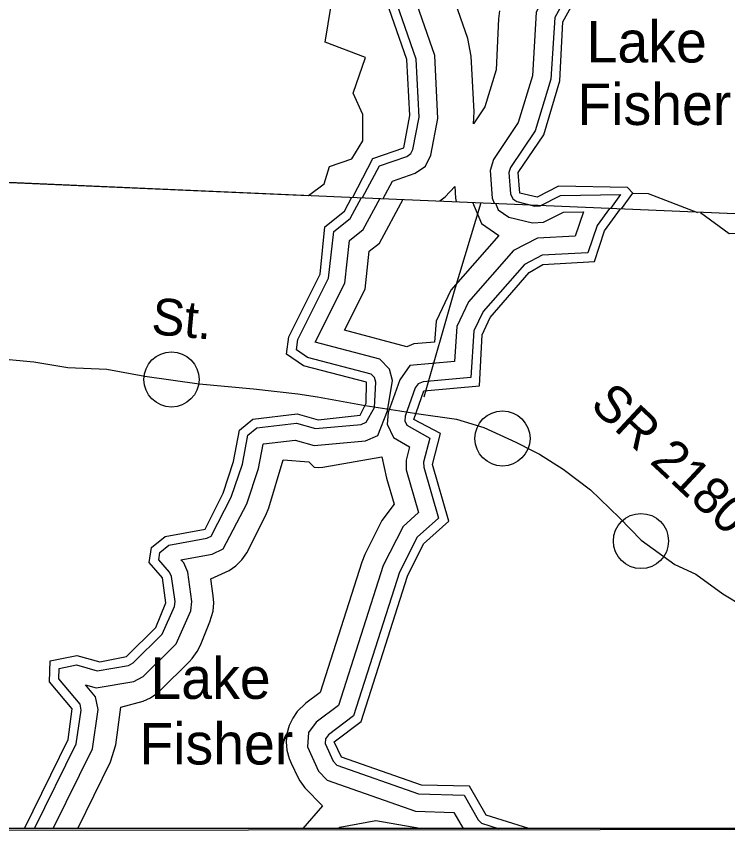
# Model space of a CAD drawing. Extents: x 1530800 to 1534168, y 642962 to 645162.
# Drawn here: x 1531509.4 to 1531702.7, y 644498.9 to 644725.7 of the extents above; entities that cross this region are included whole.
import ezdxf

# ---------------------------------------------------------------- set-up
doc = ezdxf.new("R2010")
doc.units = 0
for name, color, linetype in [('Old_Level_1', 7, 'Continuous'), ('Old_Level_11', 7, 'Continuous'), ('Old_Level_21', 7, 'Continuous'), ('Old_Level_29', 7, 'Continuous'), ('Old_Level_32', 7, 'Continuous'), ('Old_Level_49', 7, 'Continuous'), ('Old_Level_52', 7, 'Continuous'), ('Old_Level_59', 7, 'Continuous'), ('Old_Level_60', 7, 'Continuous'), ('Old_Level_61', 7, 'Continuous')]:
    doc.layers.add(name, color=color, linetype=linetype)

msp = doc.modelspace()

# ---------------------------------------------------------------- linework, layer by layer
at = {"layer": 'Old_Level_1'}
for centre in [(1531551.47, 644626.99), (1531641.5, 644610.94), (1531679.18, 644583.03)]:
    msp.add_circle(centre, 7.5, dxfattribs=at)
at = {"layer": 'Old_Level_29'}
for points in [[(1531285.1, 645044.6), (1531955.36, 645044.6), (1531955.36, 644504.86), (1531285.1, 644504.86)], [(1531285.1, 644504.21), (1531955.36, 644504.86), (1531955.44, 644422.92), (1531285.18, 644422.27)]]:
    msp.add_lwpolyline(points, close=True, dxfattribs=at)
msp.add_lwpolyline([(1531954.88, 644504.86), (1531284.62, 644504.86)], dxfattribs=at)
at = {"layer": 'Old_Level_32'}
for points in [[(1531454.41, 644646.09), (1531467.57, 644641.36), (1531481.68, 644637.23), (1531492.88, 644634.03), (1531502.42, 644632.85), (1531514.02, 644631.77), (1531523.24, 644630.23), (1531533.86, 644629.78), (1531544.2, 644627.84), (1531559.04, 644625.83), (1531573.76, 644624.43), (1531585.86, 644623.09), (1531591.22, 644622.24), (1531604.18, 644619.88), (1531613.6, 644618.44)], [(1531613.6, 644618.44), (1531618.15, 644617.75), (1531628.98, 644616.18), (1531636.45, 644613.92), (1531645.13, 644609.89), (1531649.96, 644607.45), (1531651.56, 644606.64), (1531658, 644602.61), (1531665.41, 644597), (1531673.3, 644589.37), (1531679.21, 644583.28), (1531688.35, 644576.63), (1531694.09, 644574.01), (1531701.48, 644568.68), (1531707.14, 644565.24), (1531712.46, 644561.98), (1531722.65, 644556.98)]]:
    msp.add_lwpolyline(points, dxfattribs=at)
at = {"layer": 'Old_Level_49'}
msp.add_line((1531592.97, 644680.21), (1531594.48, 644684.9), dxfattribs=at)
for points in [[(1531594.48, 644684.9), (1531600.5, 644686.97), (1531603.54, 644691.89), (1531603.54, 644699.09), (1531600.86, 644704.86), (1531604.21, 644714.56), (1531593.27, 644718.77), (1531599.26, 644755.34), (1531602.71, 644760.06), (1531597.99, 644803.72), (1531515.37, 644810.8), (1531524.81, 644837.94), (1531450.45, 644839.12), (1531323.02, 644842.1), (1531285.94, 644842.88)], [(1531285.1, 644694.34), (1531324.69, 644691.72), (1531465.61, 644682.42), (1531588.73, 644677.01)], [(1531588.73, 644677.01), (1531592.97, 644680.21)]]:
    msp.add_lwpolyline(points, dxfattribs=at)
at = {"layer": 'Old_Level_52'}
msp.add_lwpolyline([(1531954.91, 644663.36), (1531779.67, 644668.88), (1531597.73, 644676.59), (1531466.06, 644682.38), (1531325.14, 644691.67), (1531285.1, 644694.33)], dxfattribs=at)
at = {"layer": 'Old_Level_59'}
for points in [[(1531676.97, 644677.71), (1531681.16, 644677.62), (1531694.54, 644672.41)], [(1531695.36, 644672.37), (1531703.15, 644666.72), (1531711.46, 644666.76), (1531722.33, 644663.87), (1531738.34, 644670.79)]]:
    msp.add_lwpolyline(points, dxfattribs=at)
at = {"layer": 'Old_Level_60'}
for points in [[(1531676.97, 644677.71), (1531675.47, 644679.17), (1531656.72, 644679.55), (1531650.91, 644676.59), (1531646.22, 644677.71), (1531645.78, 644683.26), (1531652.72, 644693.58), (1531657.15, 644708.26), (1531657.9, 644724.25), (1531665.41, 644737.84), (1531664.47, 644742.99), (1531657.78, 644746.82), (1531660.54, 644761.62), (1531658.32, 644768.84), (1531659.3, 644785.6), (1531654.78, 644796.89), (1531652.87, 644803.15), (1531650.97, 644811.14), (1531637.08, 644811.66), (1531637.47, 644816.37), (1531655.28, 644820.32), (1531656.91, 644823.36)], [(1531600.79, 644676.58), (1531606.28, 644687.13), (1531614.66, 644690.04), (1531616.34, 644698.83), (1531615.53, 644714.03), (1531606.6, 644739.64)], [(1531568.38, 644604.7), (1531569.96, 644613.19), (1531573.64, 644616.2), (1531585.64, 644617.6), (1531591.33, 644616.05), (1531602.83, 644617.25), (1531604.46, 644620.5), (1531604.52, 644626.24), (1531587.39, 644630.69), (1531582.77, 644633.86), (1531583.39, 644638.57), (1531591.96, 644655.63), (1531593.21, 644668.53), (1531598.52, 644672.73), (1531600.53, 644676.59)], [(1531673.84, 644673.37), (1531676.97, 644677.71)], [(1531622.47, 644603.83), (1531624.64, 644612.3), (1531617.4, 644616.13), (1531620.14, 644623.87), (1531635.27, 644625.21), (1531636.02, 644639.15), (1531638.14, 644643.82), (1531648.77, 644656.12), (1531652.46, 644658.3), (1531666.52, 644659.05), (1531669.27, 644667.4), (1531673.58, 644673.38)], [(1531511.47, 644504.86), (1531523.33, 644529), (1531524.46, 644537.38), (1531518.33, 644544.69), (1531518.46, 644550.43), (1531525.77, 644551.92), (1531531.96, 644550.16), (1531539.27, 644551.65), (1531547.2, 644559.49), (1531549.96, 644566.21), (1531549.02, 644573), (1531545.4, 644577.17), (1531546.02, 644581.26), (1531549.71, 644584.27), (1531560.65, 644586.3), (1531565.52, 644596.05), (1531568.38, 644604.7)], [(1531648.64, 644504.86), (1531637.08, 644508.44), (1531632.52, 644516.33), (1531619.52, 644516.59), (1531597.7, 644524.21), (1531595.7, 644528.36), (1531603.08, 644533.95), (1531615.7, 644573.5), (1531620.02, 644582.23), (1531626.89, 644588.45), (1531622.47, 644603.83)]]:
    msp.add_lwpolyline(points, dxfattribs=at)
at = {"layer": 'Old_Level_61'}
for points in [[(1531609.07, 644676.25), (1531611.59, 644680.93), (1531617.8, 644683.09), (1531620.59, 644685.02), (1531621.99, 644687.97), (1531623.92, 644697.99), (1531623.09, 644715.13), (1531614.17, 644740.97), (1531613.93, 644758.72), (1531612.37, 644764), (1531616.87, 644775.61), (1531622.73, 644781.71), (1531624.25, 644784.72), (1531624.39, 644791.09), (1531623.48, 644794.55), (1531620.09, 644797.59), (1531623.45, 644798.22), (1531626.41, 644799.5), (1531629.89, 644803.68)], [(1531629.89, 644803.68), (1531635.89, 644798.26), (1531638.28, 644797.09), (1531642.72, 644796.21), (1531645.13, 644794.13), (1531646.74, 644790.8), (1531647.4, 644768.14), (1531649.44, 644762.86), (1531650.23, 644745.64), (1531651.75, 644741.74), (1531657.11, 644738.53), (1531650.7, 644726.92), (1531649.63, 644709.59), (1531645.78, 644696.87), (1531639.05, 644686.86), (1531638.13, 644683.82), (1531638.7, 644676.31), (1531639.25, 644674.98)], [(1531633.6, 644696.5), (1531633.82, 644699.76), (1531633.01, 644714.96), (1531632.05, 644719.79), (1531624.06, 644742.73)], [(1531603.4, 644676.48), (1531608.04, 644685.1), (1531615.48, 644687.68), (1531616.57, 644688.44), (1531617.11, 644689.57), (1531618.8, 644698.35), (1531618.03, 644714.16), (1531609.09, 644740.09)], [(1531662.79, 644738.27), (1531655.72, 644725.46), (1531654.67, 644708.69), (1531650.44, 644694.66), (1531643.7, 644684.65), (1531643.28, 644683.26), (1531643.72, 644677.51), (1531644.31, 644676.1), (1531645.37, 644675.36), (1531650.33, 644674.16), (1531651.76, 644674.24), (1531657.3, 644677.04), (1531673.58, 644677.3)], [(1531640.67, 644727.29), (1531640.42, 644725.07), (1531639.78, 644711.25), (1531636.73, 644701.16), (1531633.6, 644696.5)], [(1531624.44, 644675.61), (1531625.9, 644676.64), (1531628.52, 644679.45)], [(1531628.52, 644679.45), (1531628.77, 644676.33), (1531628.89, 644675.42)], [(1531585.45, 644635.05), (1531585.82, 644637.82), (1531594.19, 644654.51), (1531595.59, 644667.22), (1531600.07, 644670.77), (1531603.14, 644676.48)], [(1531590.57, 644637.12), (1531598.64, 644653.19), (1531599.92, 644664.83), (1531603.64, 644667.77), (1531608.21, 644676.28)], [(1531598.5, 644640.36), (1531604.13, 644651.57), (1531605.26, 644661.87), (1531608.05, 644664.08), (1531614.47, 644676.03)], [(1531673.58, 644677.3), (1531670.86, 644673.51)], [(1531670.6, 644673.52), (1531667.24, 644668.86), (1531664.68, 644661.45), (1531652.32, 644660.8), (1531647.5, 644658.27), (1531636.25, 644645.46), (1531633.75, 644640.18), (1531632.89, 644627.51), (1531619.93, 644626.36), (1531618.54, 644625.79), (1531617.79, 644624.73), (1531615.04, 644616.97), (1531614.93, 644615.7), (1531615.48, 644614.53), (1531621.73, 644611.01), (1531620.05, 644604.45), (1531620.07, 644603.14), (1531624.06, 644589.26), (1531618.34, 644584.09), (1531613.47, 644574.6), (1531600.94, 644535.47), (1531594.2, 644530.35), (1531593.35, 644529.21), (1531593.24, 644527.92), (1531595.45, 644523.12), (1531596.45, 644522.05), (1531618.69, 644514.23), (1531631.06, 644513.86), (1531634.92, 644507.19), (1531635.83, 644506.28), (1531640.34, 644504.86)], [(1531620.23, 644622.29), (1531628.48, 644651.14), (1531635.67, 644675.17)], [(1531633.37, 644675.23), (1531635.77, 644669.45), (1531640.49, 644666.16)], [(1531639.58, 644674.97), (1531640.34, 644673.13), (1531643.2, 644671.14), (1531649.65, 644669.57), (1531652.71, 644669.75), (1531658.15, 644672.5), (1531663.53, 644672.59)], [(1531663.53, 644672.59), (1531661.25, 644666.01), (1531651.04, 644665.47), (1531644.53, 644662.05), (1531632.27, 644648.08), (1531629.09, 644641.4), (1531628.45, 644631.86), (1531616.27, 644630.79)], [(1531640.49, 644666.16), (1531627.42, 644651.27), (1531623.43, 644642.88), (1531623.04, 644637.16), (1531617.4, 644636.66), (1531615.48, 644635.86)], [(1531615.48, 644635.86), (1531598.5, 644640.36)], [(1531608.12, 644632.47), (1531590.57, 644637.12)], [(1531514.25, 644504.86), (1531525.57, 644527.9), (1531526.94, 644537.05), (1531526.62, 644538.63), (1531520.85, 644545.57), (1531520.91, 644548.38), (1531525.67, 644549.35), (1531531.27, 644547.75), (1531539.77, 644549.2), (1531541.03, 644549.87), (1531548.97, 644557.71), (1531552.27, 644565.26), (1531552.43, 644566.55), (1531551.5, 644573.34), (1531550.93, 644574.6), (1531548.04, 644577.94), (1531548.34, 644579.93), (1531550.79, 644581.93), (1531561.1, 644583.85), (1531562.26, 644584.39), (1531567.75, 644594.93), (1531570.75, 644603.91), (1531572.25, 644611.83), (1531574.66, 644613.8), (1531585.46, 644615.06), (1531590.67, 644613.64), (1531603.09, 644614.76), (1531604.44, 644615.33), (1531606.69, 644619.38), (1531607.02, 644626.21), (1531606.68, 644627.49), (1531605.77, 644628.41), (1531588.45, 644633), (1531585.45, 644635.05)], [(1531519.3, 644504.86), (1531529.95, 644526.53), (1531531.53, 644537.16), (1531530.84, 644540.64), (1531528.1, 644543.94), (1531531.01, 644543.11), (1531541.26, 644544.85), (1531543.74, 644546.19), (1531552.77, 644555.1), (1531556.69, 644564.05), (1531557, 644566.58), (1531555.9, 644574.6), (1531554.8, 644577.06), (1531554.05, 644577.92), (1531562.5, 644579.5), (1531565.57, 644580.93), (1531571.94, 644593.15), (1531575.15, 644602.77), (1531576.39, 644609.36), (1531576.5, 644609.45), (1531585.11, 644610.45), (1531590.27, 644609.05), (1531604.21, 644610.31), (1531607.64, 644611.77), (1531610.19, 644618.46), (1531611.58, 644626.7), (1531610.75, 644629.82), (1531608.12, 644632.47)], [(1531616.27, 644630.79), (1531613.55, 644626.92), (1531610.37, 644617.97), (1531610.12, 644614.84), (1531611.83, 644611.16), (1531616.25, 644608.67), (1531615.31, 644605.01), (1531615.35, 644602.44), (1531618.7, 644590.79), (1531614.53, 644587.02), (1531609.08, 644576.41), (1531596.89, 644538.33), (1531590.81, 644533.71), (1531588.76, 644530.95), (1531588.43, 644527.08), (1531591.48, 644520.46), (1531593.78, 644517.97), (1531617.81, 644509.53), (1531628.28, 644509.21), (1531630.81, 644504.86)], [(1531525.96, 644504.86), (1531534.86, 644522.93), (1531536.29, 644527.62), (1531537.67, 644537.86), (1531543.74, 644539.43), (1531545.77, 644540.38), (1531547.72, 644541.74), (1531548.49, 644542.44), (1531556.29, 644550.15), (1531557.13, 644551.06), (1531558.5, 644553.02), (1531559.32, 644554.69), (1531561.92, 644561.05), (1531562.78, 644563.99), (1531562.98, 644566.25), (1531562.84, 644568.14), (1531562.2, 644572.73), (1531567.15, 644575.03), (1531569.01, 644576.33), (1531570.62, 644577.93), (1531571.95, 644579.85), (1531577.1, 644590.09), (1531577.92, 644592.06), (1531581.84, 644605.14), (1531588.8, 644604.61), (1531590.29, 644603.12), (1531591.42, 644603.02), (1531592.65, 644603.09), (1531608.65, 644605.94)], [(1531608.65, 644605.94), (1531609.98, 644600.11), (1531612.01, 644593.09), (1531608.68, 644588.63), (1531604.09, 644579.41), (1531603.24, 644577.31), (1531591.93, 644541.84), (1531588.02, 644538.89), (1531585.7, 644536.68), (1531584.44, 644534.86), (1531583.48, 644532.81), (1531582.89, 644530.61), (1531582.69, 644528.36), (1531582.89, 644526.1), (1531583.5, 644523.83), (1531584.02, 644522.59), (1531585.94, 644518.62), (1531586.37, 644517.79), (1531587.73, 644515.85), (1531592.56, 644511.02), (1531587.22, 644504.86)], [(1531619.07, 644504.86), (1531607.09, 644506.88), (1531597.28, 644505.09), (1531596.87, 644504.86)]]:
    msp.add_lwpolyline(points, dxfattribs=at)

# ---------------------------------------------------------------- texts
at = {"layer": 'Old_Level_11'}
for s, rotation, p in [('St.', 354.6581, (1531545.77, 644639.36)), ('SR 2180', 317.0378, (1531665, 644619.62))]:
    msp.add_text(s, height=10, rotation=rotation, dxfattribs=at).set_placement(p)
at = {"layer": 'Old_Level_21'}
for s, p in [('Lake', (1531664.39, 644713.22)), ('Fisher', (1531661.87, 644696.22)), ('Lake', (1531545.75, 644540.09)), ('Fisher', (1531542.72, 644522.24))]:
    msp.add_text(s, height=11.278, dxfattribs=at).set_placement(p)

doc.saveas('drawing.dxf')
